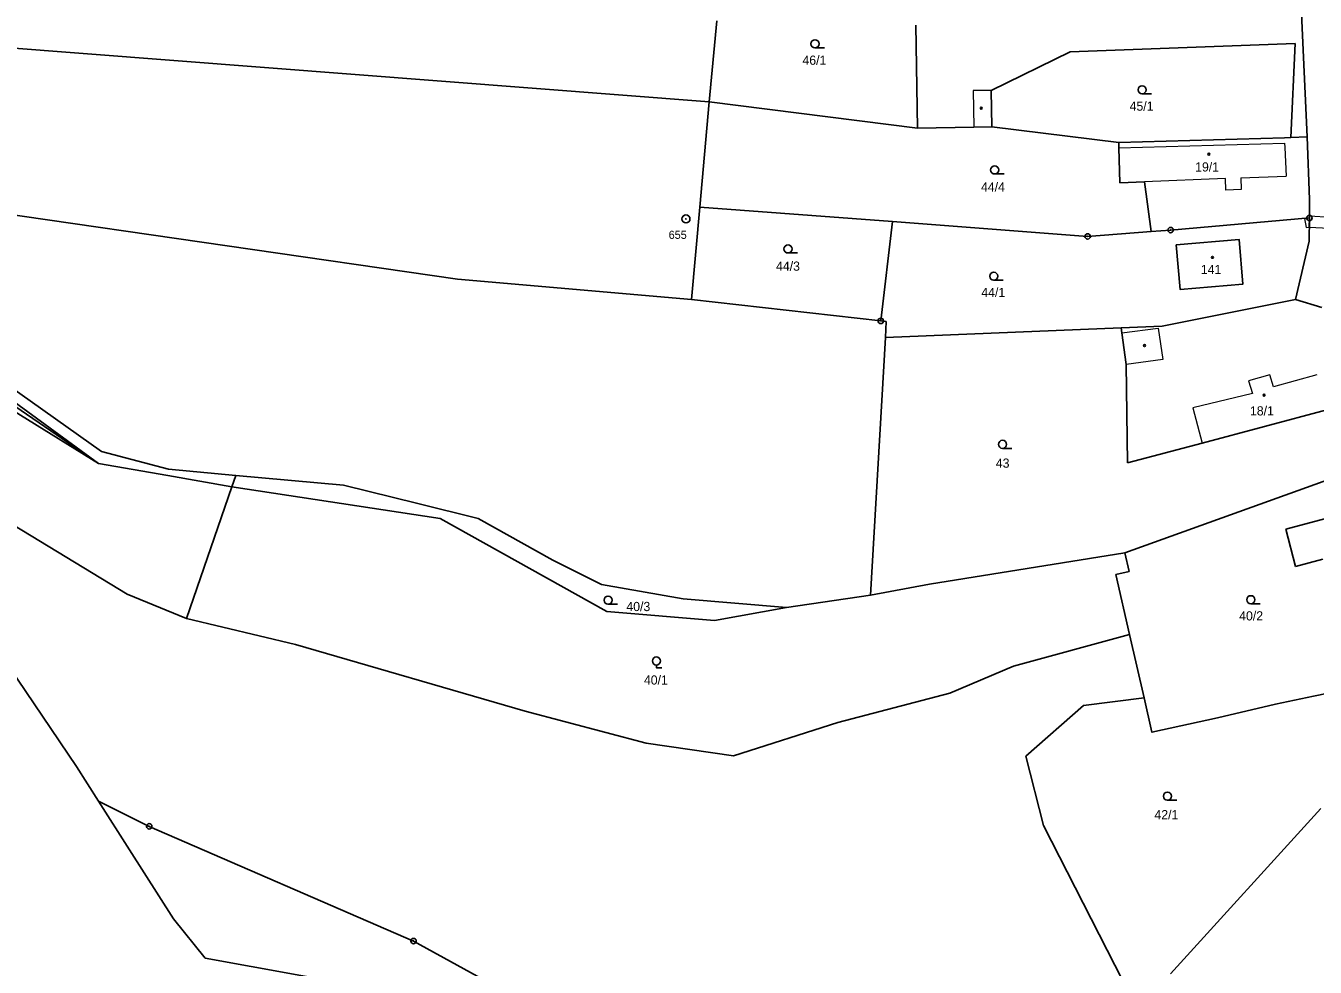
# Model space of a CAD drawing. Extents: x -645290 to -643454, y -1064771 to -1062356.
# Drawn here: x -644815.8 to -644577, y -1063831.9 to -1063657.6 of the extents above; entities that cross this region are included whole.
import ezdxf
from ezdxf.enums import TextEntityAlignment as Align

# ---------------------------------------------------------------- set-up
doc = ezdxf.new("R2010")
doc.units = 0
doc.header["$LTSCALE"] = 0.68
for name, color, linetype, lineweight in [('1', 7, 'Continuous', 25), ('13', 7, 'Continuous', 13), ('3', 7, 'Continuous', 25), ('4', 7, 'Continuous', 13), ('5', 7, 'Continuous', 25), ('8', 7, 'Continuous', 25)]:
    doc.layers.add(name, color=color, linetype=linetype, lineweight=lineweight)
doc.layers.add('2', color=7, linetype='Continuous')

msp = doc.modelspace()

# ---------------------------------------------------------------- linework, layer by layer
at = {"layer": '1'}
for p, q in [((-644579.29, -1063662.07), (-644579.62, -1063653.84)), ((-644687.82, -1063656.63), (-644689.27, -1063671.65)), ((-644650.67, -1063676.54), (-644651, -1063657.42)), ((-644835.38, -1063660.34), (-644689.27, -1063671.65)), ((-644622.38, -1063662.37), (-644637.03, -1063669.55)), ((-644580.75, -1063660.86), (-644622.38, -1063662.37)), ((-644581.55, -1063678.24), (-644580.75, -1063660.86)), ((-644578.55, -1063678.16), (-644579.29, -1063662.07)), ((-644637.03, -1063669.55), (-644636.9, -1063676.3)), ((-644690.99, -1063691.14), (-644689.27, -1063671.65)), ((-644689.27, -1063671.65), (-644650.67, -1063676.54)), ((-644640.27, -1063676.36), (-644650.67, -1063676.54)), ((-644636.9, -1063676.3), (-644640.27, -1063676.36)), ((-644613.41, -1063679.18), (-644636.9, -1063676.3)), ((-644582.74, -1063678.3), (-644613.41, -1063679.18)), ((-644613.38, -1063680.18), (-644613.41, -1063679.18)), ((-644581.55, -1063678.24), (-644582.74, -1063678.3)), ((-644578.55, -1063678.16), (-644581.55, -1063678.24)), ((-644578.55, -1063678.16), (-644578.06, -1063689.76)), ((-644613.22, -1063686.67), (-644613.38, -1063680.18)), ((-644608.62, -1063686.48), (-644613.22, -1063686.67)), ((-644607.43, -1063695.67), (-644608.62, -1063686.48)), ((-644692.5, -1063708.27), (-644690.99, -1063691.14)), ((-644690.99, -1063691.14), (-644655.32, -1063693.79)), ((-644578.06, -1063689.76), (-644578.1, -1063693.15)), ((-644822.46, -1063691.96), (-644735.89, -1063704.48)), ((-644603.81, -1063695.39), (-644578.1, -1063693.15)), ((-644578.15, -1063697.43), (-644578.1, -1063693.15)), ((-644657.48, -1063712.21), (-644655.32, -1063693.79)), ((-644655.32, -1063693.79), (-644619.17, -1063696.57)), ((-644619.17, -1063696.57), (-644607.43, -1063695.67)), ((-644607.43, -1063695.67), (-644603.81, -1063695.39)), ((-644580.67, -1063708.27), (-644578.15, -1063697.43)), ((-644735.89, -1063704.48), (-644692.5, -1063708.27)), ((-644692.5, -1063708.27), (-644657.48, -1063712.21)), ((-644580.67, -1063708.27), (-644605.37, -1063713.18)), ((-644575.8, -1063709.73), (-644580.67, -1063708.27)), ((-644657.48, -1063712.21), (-644656.49, -1063712.32)), ((-644656.49, -1063712.32), (-644656.62, -1063715.27)), ((-644837.89, -1063712.72), (-644802.37, -1063738.6)), ((-644612.96, -1063713.49), (-644656.62, -1063715.27)), ((-644605.37, -1063713.18), (-644612.96, -1063713.49)), ((-644612.83, -1063714.42), (-644612.96, -1063713.49)), ((-644612.01, -1063720.3), (-644612.83, -1063714.42)), ((-644802.37, -1063738.6), (-644838.33, -1063716.31)), ((-644801.78, -1063736.38), (-644828.89, -1063717.17)), ((-644656.62, -1063715.27), (-644659.36, -1063762.99)), ((-644802.37, -1063738.6), (-644830.45, -1063719.37)), ((-644611.78, -1063738.53), (-644612.01, -1063720.3)), ((-644574.87, -1063728.66), (-644597.97, -1063734.84)), ((-644789.37, -1063739.68), (-644801.78, -1063736.38)), ((-644597.97, -1063734.84), (-644611.78, -1063738.53)), ((-644789.48, -1063740.87), (-644802.37, -1063738.6)), ((-644563.78, -1063737.68), (-644612.27, -1063755.14)), ((-644777.65, -1063742.95), (-644789.48, -1063740.87)), ((-644776.92, -1063740.82), (-644789.37, -1063739.68)), ((-644776.92, -1063740.82), (-644777.65, -1063742.95)), ((-644756.99, -1063742.65), (-644776.92, -1063740.82)), ((-644777.65, -1063742.95), (-644786.06, -1063767.32)), ((-644777.65, -1063742.95), (-644739.06, -1063748.8)), ((-644743.23, -1063746.04), (-644756.99, -1063742.65)), ((-644732.04, -1063748.83), (-644743.23, -1063746.04)), ((-644582.49, -1063750.8), (-644568.82, -1063747.14)), ((-644797.01, -1063762.84), (-644819.68, -1063749.08)), ((-644739.06, -1063748.8), (-644708.19, -1063766.05)), ((-644718.18, -1063756.54), (-644732.04, -1063748.83)), ((-644580.65, -1063757.69), (-644582.49, -1063750.8)), ((-644612.27, -1063755.14), (-644648.43, -1063760.98)), ((-644611.49, -1063758.63), (-644612.27, -1063755.14)), ((-644709.17, -1063761.04), (-644718.18, -1063756.54)), ((-644575.59, -1063756.34), (-644580.65, -1063757.69)), ((-644694.09, -1063763.66), (-644709.17, -1063761.04)), ((-644648.43, -1063760.98), (-644659.36, -1063762.99)), ((-644786.06, -1063767.32), (-644797.01, -1063762.84)), ((-644674.96, -1063765.3), (-644694.09, -1063763.66)), ((-644659.36, -1063762.99), (-644674.96, -1063765.3)), ((-644765.85, -1063772.14), (-644786.06, -1063767.32)), ((-644708.19, -1063766.05), (-644688.27, -1063767.69)), ((-644688.27, -1063767.69), (-644674.96, -1063765.3)), ((-644765.85, -1063772.14), (-644723.35, -1063784.46)), ((-644611.4, -1063770.28), (-644632.92, -1063776.17)), ((-644611.4, -1063770.28), (-644608.73, -1063782)), ((-644820.53, -1063773.82), (-644806.4, -1063794.75)), ((-644644.72, -1063781.14), (-644632.92, -1063776.17)), ((-644577.34, -1063781.7), (-644556.45, -1063777.39)), ((-644665.45, -1063786.6), (-644644.72, -1063781.14)), ((-644584.37, -1063783.2), (-644577.34, -1063781.7)), ((-644630.62, -1063792.83), (-644619.97, -1063783.46)), ((-644619.97, -1063783.46), (-644608.73, -1063782)), ((-644595.11, -1063785.75), (-644584.37, -1063783.2)), ((-644723.35, -1063784.46), (-644700.93, -1063790.42)), ((-644684.77, -1063792.76), (-644665.45, -1063786.6)), ((-644700.93, -1063790.42), (-644684.77, -1063792.76)), ((-644630.62, -1063792.83), (-644627.33, -1063805.69)), ((-644806.4, -1063794.75), (-644802.32, -1063801.15)), ((-644802.32, -1063801.15), (-644796.58, -1063810.18)), ((-644792.94, -1063805.82), (-644802.32, -1063801.15)), ((-644575.96, -1063802.49), (-644603.81, -1063833.16)), ((-644627.33, -1063805.69), (-644606.6, -1063846.26)), ((-644744, -1063827.06), (-644792.94, -1063805.82)), ((-644796.58, -1063810.18), (-644788.47, -1063822.92)), ((-644788.47, -1063822.92), (-644782.57, -1063830.25)), ((-644711.45, -1063844.95), (-644744, -1063827.06)), ((-644782.57, -1063830.25), (-644756.35, -1063834.98))]:
    msp.add_line(p, q, dxfattribs=at)
msp.add_lwpolyline([(-644602.75, -1063698.16), (-644591.14, -1063697.14), (-644590.42, -1063705.39), (-644602.02, -1063706.42)], close=True, dxfattribs=at)
for points in [[(-644611.4, -1063770.28), (-644613.94, -1063759.18), (-644611.49, -1063758.63)], [(-644608.73, -1063782), (-644607.28, -1063788.38), (-644595.11, -1063785.75)]]:
    msp.add_lwpolyline(points, dxfattribs=at)
at = {"layer": '13'}
for points in [[(-644578.12, -1063694.85), (-644578.1, -1063693.15), (-644579, -1063693.23), (-644578.68, -1063694.95)], [(-644578.1, -1063693.15), (-644578.12, -1063694.85), (-644574.42, -1063695.06), (-644574.22, -1063693.07), (-644578.1, -1063692.82)]]:
    msp.add_lwpolyline(points, close=True, dxfattribs=at)
at = {"layer": '3'}
for p, q in [((-644669.663, -1063661.66), (-644667.913, -1063661.66)), ((-644609.083, -1063670.17), (-644607.333, -1063670.17)), ((-644636.393, -1063685.01), (-644634.643, -1063685.01)), ((-644674.653, -1063699.64), (-644672.903, -1063699.64)), ((-644636.553, -1063704.69), (-644634.803, -1063704.69)), ((-644634.933, -1063735.83), (-644633.183, -1063735.83)), ((-644707.973, -1063764.68), (-644706.223, -1063764.68)), ((-644588.953, -1063764.6), (-644587.203, -1063764.6)), ((-644604.393, -1063800.98), (-644602.643, -1063800.98))]:
    msp.add_line(p, q, dxfattribs=at)
msp.add_lwpolyline([(-644699.03, -1063775.942), (-644699.03, -1063776.44), (-644698.029, -1063776.44)], dxfattribs=at)
for centre in [(-644669.6629, -1063660.9098), (-644609.0829, -1063669.4198), (-644636.3929, -1063684.2598), (-644674.6529, -1063698.8898), (-644636.5529, -1063703.9398), (-644634.9329, -1063735.0798), (-644707.9729, -1063763.9298), (-644588.9529, -1063763.8498), (-644699.0293, -1063775.1909), (-644604.3929, -1063800.2298)]:
    msp.add_circle(centre, 0.75, dxfattribs=at)
at = {"layer": '4'}
for p, q in [((-644613.38, -1063680.18), (-644582.69, -1063679.31)), ((-644582.69, -1063679.31), (-644582.64, -1063680.09)), ((-644582.64, -1063680.09), (-644582.38, -1063685.41)), ((-644593.67, -1063685.87), (-644608.62, -1063686.48)), ((-644593.59, -1063688.01), (-644593.67, -1063685.87)), ((-644590.82, -1063685.75), (-644582.38, -1063685.41)), ((-644590.82, -1063685.75), (-644590.73, -1063687.9)), ((-644590.73, -1063687.9), (-644593.59, -1063688.01)), ((-644612.83, -1063714.42), (-644606.09, -1063713.57)), ((-644606.09, -1063713.57), (-644605.25, -1063719.36)), ((-644605.25, -1063719.36), (-644612.01, -1063720.3)), ((-644585.43, -1063722.19), (-644589.36, -1063723.31)), ((-644584.73, -1063724.44), (-644585.43, -1063722.19)), ((-644576.72, -1063722.21), (-644584.73, -1063724.44)), ((-644589.36, -1063723.31), (-644588.67, -1063725.67)), ((-644588.67, -1063725.67), (-644599.7, -1063728.33)), ((-644599.7, -1063728.33), (-644597.97, -1063734.84))]:
    msp.add_line(p, q, dxfattribs=at)
msp.add_lwpolyline([(-644637.03, -1063669.55), (-644640.38, -1063669.56), (-644640.27, -1063676.36)], dxfattribs=at)
at = {"layer": '5'}
for centre in [(-644638.8668, -1063672.8292), (-644596.7168, -1063681.3492), (-644596.0668, -1063700.4492), (-644608.6268, -1063716.7892), (-644586.5068, -1063725.9892)]:
    msp.add_circle(centre, 0.175, dxfattribs=at)
at = {"layer": '8'}
for centre, radius in [((-644693.56, -1063693.3298), 0.75), ((-644693.56, -1063693.3298), 0.03), ((-644578.1, -1063693.1499), 0.5), ((-644578.1, -1063693.1499), 0.0303), ((-644603.81, -1063695.3899), 0.5), ((-644603.81, -1063695.3899), 0.0303), ((-644619.17, -1063696.5699), 0.5), ((-644619.17, -1063696.5699), 0.0303), ((-644657.48, -1063712.2099), 0.5), ((-644657.48, -1063712.2099), 0.0303), ((-644792.94, -1063805.8199), 0.5), ((-644792.94, -1063805.8199), 0.0303), ((-644744, -1063827.0599), 0.5), ((-644744, -1063827.0599), 0.0303)]:
    msp.add_circle(centre, radius, dxfattribs=at)

# ---------------------------------------------------------------- texts
at = {"layer": '2'}
for s, p in [('46/1', (-644669.769, -1063664.785)), ('45/1', (-644609.189, -1063673.295)), ('19/1', (-644597.049, -1063684.554)), ('44/3', (-644674.659, -1063702.925)), ('141', (-644596.309, -1063703.545)), ('44/1', (-644636.659, -1063707.795)), ('18/1', (-644586.899, -1063729.725)), ('43', (-644634.909, -1063739.405)), ('40/2', (-644588.899, -1063767.685)), ('40/1', (-644699.129, -1063779.564)), ('42/1', (-644604.589, -1063804.505))]:
    msp.add_text(s, height=1.7, dxfattribs=at).set_placement(p, align=Align.CENTER)
for s, p in [('44/4', (-644638.92, -1063688.265)), ('40/3', (-644704.59, -1063765.955))]:
    msp.add_text(s, height=1.7, dxfattribs=at).set_placement(p)
at = {"layer": '8'}
msp.add_text('655', height=1.5, dxfattribs=at).set_placement((-644696.76, -1063697.024))

doc.saveas('drawing.dxf')
